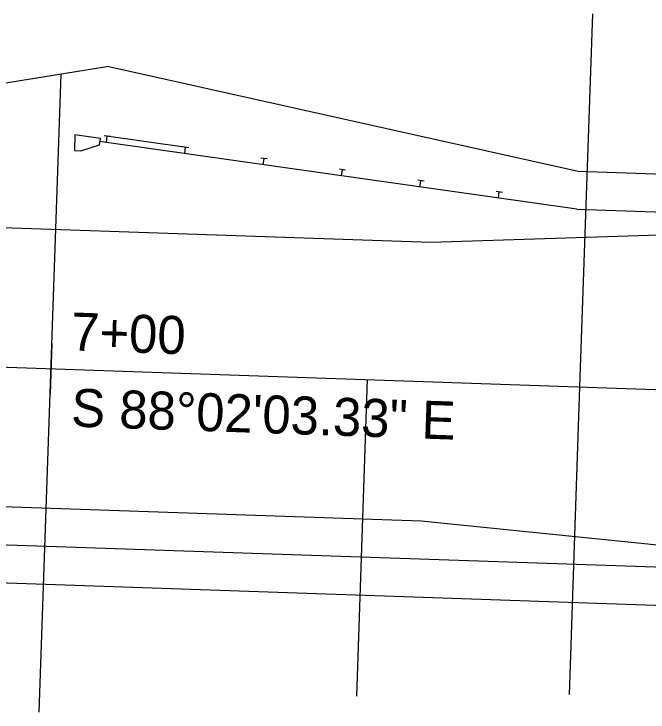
# Model space of a CAD drawing. Extents: x 2191309 to 2193046, y 863659 to 865133.
# Drawn here: x 2191615.2 to 2191665.3, y 865062.5 to 865117.6 of the extents above; entities that cross this region are included whole.
import ezdxf

# ---------------------------------------------------------------- set-up
doc = ezdxf.new("R2010")
doc.units = 0
for name, color, linetype in [('D_Guardrail_Beam_Lt', 7, 'Continuous'), ('D_Guardrail_Beam_Rt', 7, 'Continuous'), ('D_Guardrail_End_MidSplice', 7, 'Continuous'), ('D_Roadway_Centerline', 7, 'Continuous'), ('D_Roadway_Centerline_Bearings', 7, 'Continuous'), ('D_Roadway_Centerline_Text', 7, 'Continuous'), ('D_Roadway_Edge_Shoulder', 7, 'Continuous'), ('D_Roadway_Edge_TW', 7, 'Continuous'), ('JUNK', 7, 'Continuous')]:
    doc.layers.add(name, color=color, linetype=linetype)

msp = doc.modelspace()

# ---------------------------------------------------------------- linework, layer by layer
at = {"layer": 'D_Guardrail_Beam_Lt'}
msp.add_line((2191659.631, 865102.165), (2191669, 865101.843), dxfattribs=at)
at = {"layer": 'D_Guardrail_Beam_Rt'}
msp.add_line((2191596.207, 865076.325), (2191668.04, 865073.86), dxfattribs=at)
at = {"layer": 'D_Guardrail_End_MidSplice'}
for p, q in [((2191620.023, 865108.046), (2191619.98, 865106.797)), ((2191622.044, 865107.759), (2191620.023, 865108.046)), ((2191621.974, 865107.264), (2191622.044, 865107.759)), ((2191622.504, 865107.441), (2191622.009, 865107.512)), ((2191622.822, 865107.901), (2191622.327, 865107.971)), ((2191629.01, 865107.022), (2191622.327, 865107.971)), ((2191622.504, 865107.441), (2191622.574, 865107.936)), ((2191659.631, 865102.165), (2191622.504, 865107.441)), ((2191620.48, 865106.78), (2191621.974, 865107.264)), ((2191629.01, 865107.022), (2191628.515, 865107.092)), ((2191628.692, 865106.562), (2191628.762, 865107.057)), ((2191619.98, 865106.797), (2191620.48, 865106.78)), ((2191635.197, 865106.142), (2191634.702, 865106.213)), ((2191634.88, 865105.682), (2191634.95, 865106.177)), ((2191641.385, 865105.263), (2191640.89, 865105.333)), ((2191641.067, 865104.803), (2191641.138, 865105.298)), ((2191647.573, 865104.383), (2191647.078, 865104.454)), ((2191647.255, 865103.923), (2191647.326, 865104.419)), ((2191653.761, 865103.504), (2191653.266, 865103.574)), ((2191653.443, 865103.044), (2191653.513, 865103.539))]:
    msp.add_line(p, q, dxfattribs=at)
at = {"layer": 'D_Roadway_Centerline'}
msp.add_line((2191489.641, 865093.991), (2191792.637, 865083.591), dxfattribs=at)
at = {"layer": 'D_Roadway_Centerline_Text'}
msp.add_lwpolyline([(2191618.199, 865091.58), (2191618.062, 865087.582)], dxfattribs=at)
at = {"layer": 'D_Roadway_Edge_Shoulder'}
for p, q in [((2191622.71, 865113.438), (2191568.619, 865104.685)), ((2191622.71, 865113.438), (2191659.734, 865105.163)), ((2191659.734, 865105.163), (2191698.167, 865103.844)), ((2191596.104, 865073.327), (2191697, 865069.864))]:
    msp.add_line(p, q, dxfattribs=at)
at = {"layer": 'D_Roadway_Edge_TW'}
for points in [[(2191518.589, 865104.656), (2191543.552, 865103.147), (2191648.101, 865099.559), (2191698.075, 865101.179)], [(2191517.799, 865081.655), (2191542.797, 865081.16), (2191647.347, 865077.572), (2191697.092, 865072.529)]]:
    msp.add_lwpolyline(points, dxfattribs=at)
at = {"layer": 'JUNK'}
for p, q in [((2191660.866, 865117.582), (2191659.856, 865088.149)), ((2191617.2, 865062.489), (2191618.928, 865112.826)), ((2191642.258, 865063.737), (2191643.116, 865088.723)), ((2191659.856, 865088.149), (2191659.023, 865063.874))]:
    msp.add_line(p, q, dxfattribs=at)

# ---------------------------------------------------------------- texts
at = {"layer": 'D_Roadway_Centerline_Bearings'}
msp.add_text('S 88%%d02\'03.33" E', height=3, rotation=358.0343, dxfattribs=at).set_placement((2191619.697, 865085.024))
at = {"layer": 'D_Roadway_Centerline_Text'}
msp.add_text('7+00', height=3, rotation=358.0343, dxfattribs=at).set_placement((2191619.681, 865091.028))

doc.saveas('drawing.dxf')
